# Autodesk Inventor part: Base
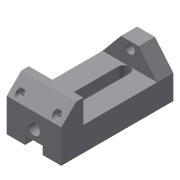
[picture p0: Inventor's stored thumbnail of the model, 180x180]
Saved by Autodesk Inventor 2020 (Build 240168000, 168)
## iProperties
Created: 2002-02
Part Number: Base
Document SubType Name: Modeling
Designer: ***
Density: 1 g/cm^3
Material: Generic
Appearance: Default
Control State: 0
Master: False
Checked Out: False
Shininess: 77.0
Length Units: 11269
Angle Units: 11279
Time Units: 11290
Mass Units: 11283
Length Display Precision: 3
Angle Display Precision: 2
Density: 0.0
Volumn: 0.0
Area: 0.0
PropertySet Name: Model Information
Author: ***
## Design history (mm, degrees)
sketch "Sketch2"
  geometry: L1 (-63.961, -4.254)-(-63.961, -37.254); L2 (-63.961, -37.254)-(88.039, -37.254); L3 (88.039, -37.254)-(88.039, 7.746); L4 (88.039, 7.746)-(68.039, 27.746); L5 (68.039, 27.746)-(58.039, 27.746); L6 (58.039, 27.746)-(58.039, -4.254); L7 (58.039, -4.254)-(-63.961, -4.254)
  constraints: 14 end point, 4 parallel, 1 perpendicular, 1 vertical
  dimensions: "d7" = 10 distance of L4.end L5.end; "d8" = 135 deg angle of L3 L4; "d9" = 33 distance of L1.start L1.end; "d10" = 152 distance of L1.end L2.end; "d11" = 65 distance between parallel lines of L5 L2; "d21" = 30 distance between parallel lines of L3 L6
extrude "Extrusion1" new body sketch "Sketch2" stored distance "d13" = 74; taper "d14" = 0 deg
sketch "Sketch3"
  geometry: L1 (0, 74)-(0, 0) reference; L2 (0, 0)-(-30, 25); L3 (-30, 25)-(-30, 49); L4 (-30, 49)-(0, 74); C1 r 6.5 at (-21, 37)
  constraints: 6 end point, 1 centre point, 1 equal length, 1 parallel
  dimensions: "d15" = 24 distance of L2.end L3.end; "d16" = 30 distance between parallel lines of L3 L1; "d17" = 13 diameter of C1; "d18" = 9 distance from line of L3 C1.centre
extrude "Extrusion2" join sketch "Sketch3" distance "d19" = 22; taper "d20" = 0 deg
sketch "Sketch4"
  geometry: L1 (0, 0)-(0, 74) reference; L2 (0, 0)-(45, 0) reference; C1 r 8 at (25, 37)
  constraints: 1 centre point
  dimensions: "d22" = 16 diameter of C1; "d23" = 25 distance from line of L1 C1.centre; "d24" = 37 distance from line of L2 C1.centre
extrude "Extrusion3" cut sketch "Sketch4" distance "d25" = 13; taper "d26" = 0 deg
sketch "Sketch5"
  geometry: L1 (45, 74)-(0, 74) reference; L2 (65, 0)-(65, 74) reference; 1 further point
  dimensions: "d27" = 12 distance from line of point (51, 62) L1; "d28" = 14 distance from line of L2 point (51, 62)
hole "Hole1" sketch "Sketch5" at (51, 62) diameter "d29" = 4.917; stored, may be unused: countersink angle "d33" = 82 deg, drill point angle "d35" = 0 deg; dims "d30" = 12, "d31" = 10, "d32" = 10, "d34" = 45
mirror "Mirror1"
sketch "Sketch6"
  geometry: L1 (100, 0)-(100, 74) reference; L2 (100, 74)-(0, 74) reference; L3 (14, 45)-(92, 45); L4 (92, 29)-(14, 29); A1 r 8 centre (92, 37) between (92, 29) and (92, 45); A2 r 8 centre (14, 37) between (14, 45) and (14, 29)
  constraints: 4 end point, 4 point on circle, 4 tangent, 2 centre point, 1 horizontal, 1 parallel
  dimensions: "d36" = 8 radius of A2; "d37" = 78 distance of L4.start L4.end; "d38" = 8 distance from line of L1 A1.centre; "d39" = 37 distance from line of L2 A2.centre
extrude "Extrusion4" cut sketch "Sketch6" extent not by distance; stored distance "d40" = 13; taper "d41" = 0 deg
sketch "Sketch7"
  geometry: L1 (45, 74)-(0, 74) reference; L2 (11, 49)-(0, 49); L3 (0, 49)-(0, 25); L4 (0, 25)-(11, 25); L5 (11, 25)-(11, 49); L6 (0, 0)-(45, 0) reference; L7 (0, 0)-(0, 74) reference
  constraints: 8 end point, 2 parallel, 1 collinear, 1 horizontal, 1 perpendicular
  dimensions: "d47" = 11 distance of L3.end L4.end; "d48" = 25 distance between parallel lines of L6 L4; "d49" = 24 distance of L2.end L3.end
extrude "Extrusion5" cut sketch "Sketch7" extent not by distance; stored distance "d45" = 13; taper "d46" = 0 deg
body "Solid1"
